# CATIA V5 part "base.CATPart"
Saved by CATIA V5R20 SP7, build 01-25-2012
Part number: base
Publications: "pivot_base_AB", "pivot_base_CD", "pivot_base_FG", "Plan_Ref"
Bounding box of the stored display mesh (mm): x -50 to 50, y -80 to 779.835, z -105 to 295
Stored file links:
  G:\IAO\apres\base.CATPart
  G:\IAO\apres\psedsuay.CATProduct
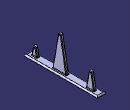
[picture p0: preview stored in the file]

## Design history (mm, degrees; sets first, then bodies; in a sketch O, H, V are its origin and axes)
External parameters (linked from other documents)
  External.Diametre = 30 mm
  External.Longueur_AB = 100 mm
  External.Diametre_pivot = 10 mm
  External.Epaisseur = 4 mm
Set1
  Point1 "Point_A": linked copy from another document
  Plane1 "Plan_Ref": linked copy from another document
  Point2 "Point_D": linked copy from another document
  Point3 "Point_G": linked copy from another document
  Plane2: linked copy from another document
Set2 "skelette"
  Line1 "pivot_base_AB": type Normal, RefPoint Point1, RefSkin Plane1, Start -20, End 20
  Line2 "pivot_base_CD": type Normal, RefPoint Point2, RefSkin Plane1, Start -20, End 20
  Line3 "pivot_base_FG": type Normal, RefPoint Point3, RefSkin Plane1, Start -20, End 20
Set3 "piece"
  Sketch1 on Plane2, origin (0, 0, 0), H (0, 1, 0), V (0, 0, 1)
    arc A1 centre (300, 280) radius 15 from (314.7721, 282.6047) to (285.2279, 282.6047) ccw
    arc A2 centre (659.8349, 82.7215) radius 15 from (674.6071, 85.3262) to (645.0628, 85.3262) ccw
    reference projected point E1 (300, 280) from Point1
    reference projected point E2 (659.8349, 82.7215) from Point2
    line L1 (285.2279, 282.6047) -> (219.5276, -90)
    line L2 (380.4724, -90) -> (314.7721, 282.6047)
    line L3 (645.0628, 85.3262) -> (614.1481, -90)
    line L4 (674.6071, 85.3262) -> (705.5218, -90)
    line L5 (219.5276, -90) -> (380.4724, -90)
    point P9 (614.1481, -90)
    line L6 (614.1481, -90) -> (705.5218, -90)
    reference projected point E3 (0, 0) from Point3
    radius A2 = 15 {= External.Diametre /2}
    radius A1 = 15 {= External.Diametre /2}
    angle L1 L5 = 100
    angle L2 L5 = 100
    angle L3 L6 = 100
    angle L4 L6 = 100
    distance L5 E3 = 90 {= 0.9*External.Longueur_AB}
    concentricity: A1 E1, A2 E2
    tangency: L1 A1, L2 A1, L3 A2, L4 A2
    horizontal: L5 H, L6 H
    coincidence: L5 P9, L5 L6
  Plane3: type OffsetPt, RefPlane xy-plane, RefPoint Point3
  Plane4: type Offset, RefPlane Plane3, Offset 90 {= 0.9*External.Longueur_AB}, reversed
  Sketch2 on Plane4, origin (0, 0, -90), H (1, 0, 0), V (0, 1, 0)
    line L1 (-50, 779.8349) -> (50, 779.8349)
    line L2 (50, 779.8349) -> (50, -80)
    line L3 (50, -80) -> (-50, -80)
    line L4 (-50, -80) -> (-50, 779.8349)
    reference projected point E1 (0, 0) from Point3
    reference projected point E2 (0, 659.8349) from Point2
    distance L3 E1 = 80 {= 0.8*External.Longueur_AB}
    distance L1 E2 = 120 {= 1.2*External.Longueur_AB}
    distance L2 L4 = 100 {= External.Longueur_AB}
    horizontal: L1 H, L3 H
    vertical: L2 V, L4 V
    symmetry: L4 L2 V
  Sketch3 on Plane2, origin (0, 0, 0), H (0, 1, 0), V (0, 0, 1)
    arc A1 centre (0, 0) radius 15 from (14.7721, 2.6047) to (-14.7721, 2.6047) ccw
    line L1 (-31.1008, -90) -> (31.1008, -90)
    line L2 (-31.1008, -90) -> (-14.7721, 2.6047)
    line L3 (31.1008, -90) -> (14.7721, 2.6047)
    reference projected point E1 (0, 0) from Line3
    reference projected point E2 (0, 0) from Point3
    angle L3 L1 = 100
    angle L1 L2 = 100
    radius A1 = 15 {= External.Diametre  /2}
    distance L1 E2 = 90 {= 0.9*External.Longueur_AB}
    horizontal: L1 H
    tangency: L2 A1, L3 A1
    concentricity: E1 A1
Body1 (main body)
  Pad1: profile Sketch1, direction (1, 0, 0), length 15 {= 0.15*External.Longueur_AB}, opposite side length 15 {= 0.15*External.Longueur_AB}
  Pad2: profile Sketch3, direction (1, 0, 0), length 11 {= 0.15*External.Longueur_AB -External.Epaisseur}, opposite side length 19 {= 0.15*External.Longueur_AB +External.Epaisseur}
  Pad3: profile Sketch2, direction (0, 0, -1), length 15 {= 0.15*External.Longueur_AB}
  Fillet1: radius 15 {= 0.15*External.Longueur_AB}, on edge [face of Pad3 from Sketch2.L2 | start face of Pad3]; edge [face of Pad3 from Sketch2.L3 | start face of Pad3]; edge [face of Pad3 from Sketch2.L4 | start face of Pad3]; edge [face of Pad3 from Sketch2.L1 | start face of Pad3]
  Fillet2: radius 6 {= 0.06*External.Longueur_AB}, on end face of Pad2; start face of Pad2; edge [face of Pad2 from Sketch3.L3 | start face of Pad3]; edge [start face of Pad3 | face of Pad2 from Sketch3.L2]
  Fillet3: radius 6 {= 0.06*External.Longueur_AB}, on end face of Pad1; edge [start face of Pad3 | face of Pad1 from Sketch1.L1]; edge [face of Pad1 from Sketch1.L2 | start face of Pad3]; start face of Pad1
  Fillet4: radius 6 {= 0.06*External.Longueur_AB}, on end face of Pad1; edge [start face of Pad3 | face of Pad1 from Sketch1.L3]; edge [face of Pad1 from Sketch1.L4 | start face of Pad3]; start face of Pad1
  Sketch4 on end face of Pad1, origin (15, -4.2016, -42.8466), H (0, 1, 0), V (0, 0, 1)
    point P1 (4.2016, 42.8466)
    reference projected point E1 (4.2016, 42.8466) from Line3
    coincidence: P1 E1
  Hole1: placed by Sketch4, at (15, 0, 0) direction (-1, 0, 0), diameter 10 {= External.Diametre_pivot}, through (limit type 3)
  Sketch5 on end face of Pad1, origin (15, 302.1432, 211.8317), H (0, 1, 0), V (0, 0, 1)
    point P1 (-2.1432, 68.1683)
    reference projected point E1 (-2.1432, 68.1683) from Line1
    coincidence: P1 E1
  Hole2: placed by Sketch5, at (15, 300, 280) direction (-1, 0, 0), diameter 10 {= External.Diametre_pivot}, through (limit type 3)
  Sketch6 on end face of Pad1, origin (15, 664.0153, 15.7745), H (0, 1, 0), V (0, 0, 1)
    point P1 (-4.1803, 66.947)
    reference projected point E1 (-4.1803, 66.947) from Line2
    coincidence: P1 E1
  Hole3: placed by Sketch6, at (15, 659.8349, 82.7215) direction (-1, 0, 0), diameter 10 {= External.Diametre_pivot}, through (limit type 3)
